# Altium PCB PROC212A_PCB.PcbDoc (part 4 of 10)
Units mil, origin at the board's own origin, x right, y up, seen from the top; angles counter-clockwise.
Board outline 3032.48 x 3598.78 mil, 4 copper layers (Top Layer, L2_GND1, L3_PWR1, Bottom Layer), stack 60.58 mil thick; 432 components, 310 nets, 7775 pads, 1236 vias.
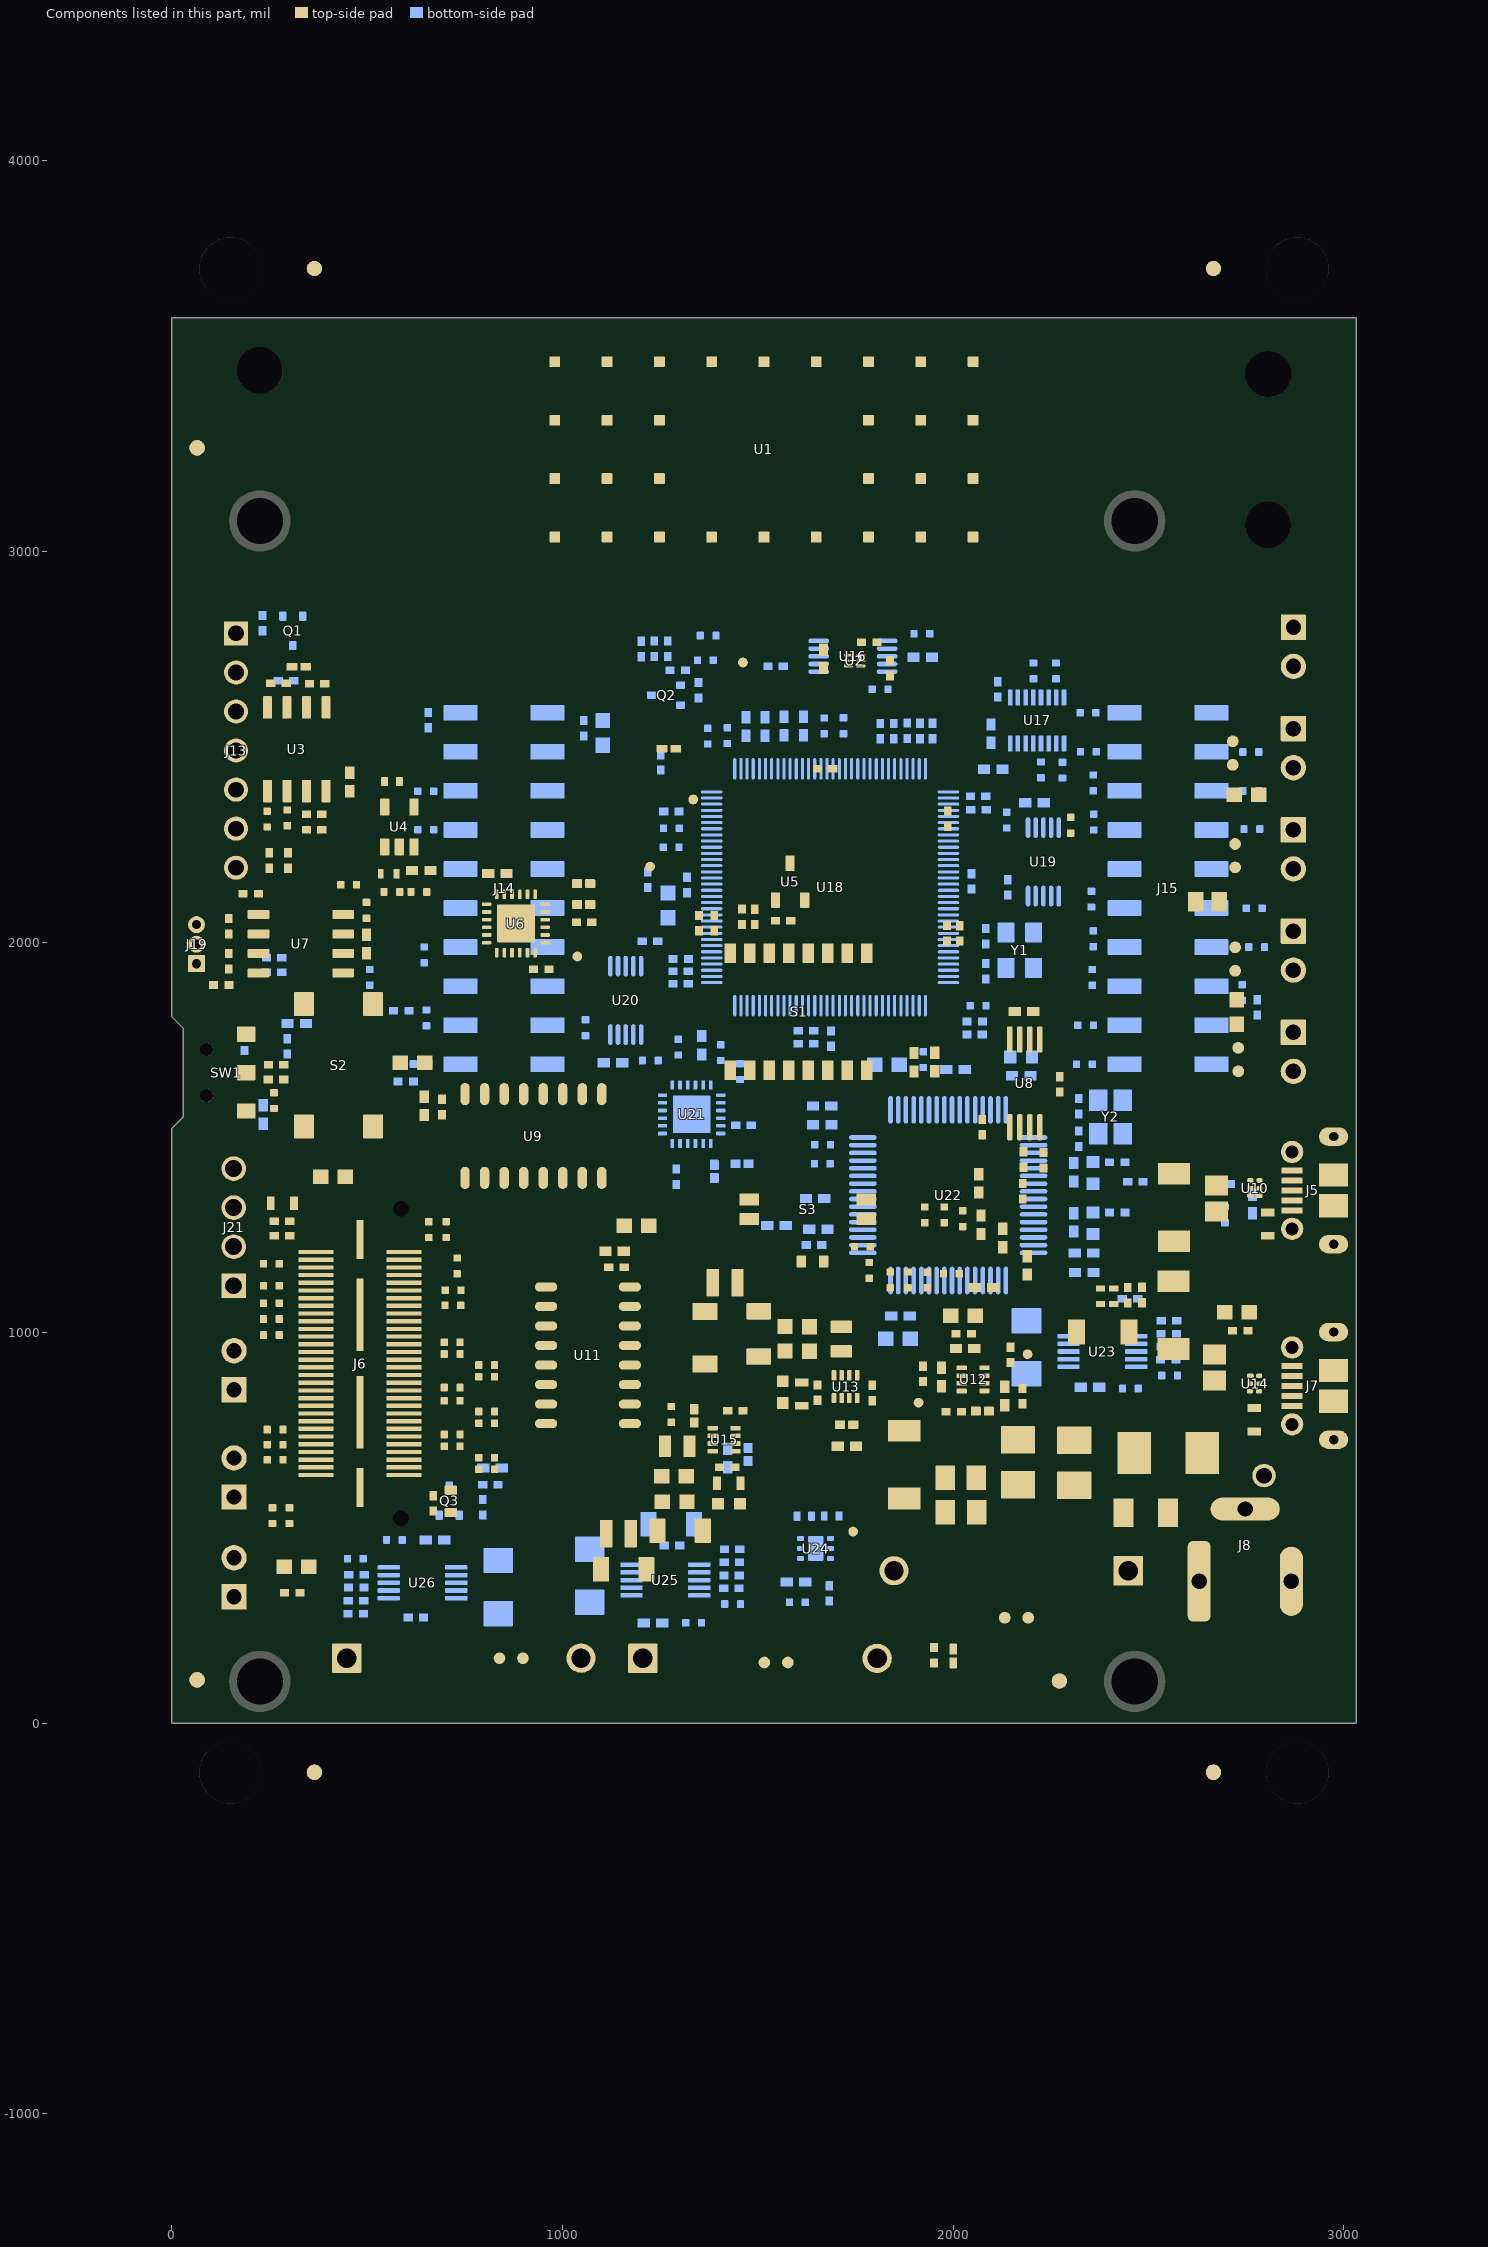
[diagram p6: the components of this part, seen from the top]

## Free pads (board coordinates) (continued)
  round 6 on Mech16: 1(585.22,1972.52) 1(585.22,1972.52) 1(585.22,2004.02) 1(585.22,2004.02) 1(589.23,1869.52) 1(589.23,1869.52) 1(589.23,1901.02) 1(589.23,1901.02) 1(598.22,1670.52) 1(598.22,1670.52) 1(598.22,1702.02) 1(598.22,1702.02) 1(600.22,1772.52) 1(600.22,1772.52) 1(600.22,1804.02) 1(600.22,1804.02) 1(605.74,1972.52) 1(605.74,2004.02) 1(609.76,1869.52) 1(609.76,1901.02) 1(618.75,1670.52) 1(618.75,1702.02) 1(620.75,1772.52) 1(620.75,1804.02) 1(623.74,1972.52) 1(623.74,2004.02) 1(627.76,1869.52) 1(627.76,1901.02) 1(630.28,289.75) 1(631.28,339.75) 1(633.28,341.75) 1(633.28,341.75) 1(633.28,389.75) 1(633.28,389.75) 1(636.75,1670.52) 1(636.75,1702.02) 1(638.75,1772.52) 1(638.75,1804.02) 1(644.27,1972.52) 1(644.27,1972.52) 1(644.27,2004.02) 1(644.27,2004.02) 1(644.28,289.75) 1(644.28,289.75) 1(644.28,400.75) 1(648.29,1869.52) 1(648.29,1869.52) 1(648.29,1901.02) 1(648.29,1901.02) 1(657.28,1670.52) 1(657.28,1670.52) 1(657.28,1702.02) 1(657.28,1702.02) 1(659.28,1772.52) 1(659.28,1772.52) 1(659.28,1804.02) 1(659.28,1804.02) 1(659.28,304.75) 1(710,1170.75) 1(710,1170.75) 1(710,1191.28) 1(710,1209.28) 1(710,1229.81) 1(710,1229.81) 1(713.28,1148.75) 1(741.5,1170.75) 1(741.5,1170.75) 1(741.5,1191.28) 1(741.5,1209.28) 1(741.5,1229.81) 1(741.5,1229.81) 1(745.28,1148.75) 1(745.28,1148.75) 1(746.28,1149.75) 1(814.37,1002.35) 1(814.37,1002.35) 1(814.37,1022.88) 1(814.37,1040.88) 1(814.37,1061.4) 1(814.37,1061.4) 1(814.37,1072.35) 1(814.37,1072.35) 1(814.37,1092.88) 1(814.37,1110.88) 1(814.37,1131.4) 1(814.37,1131.4) 1(845.87,1002.35) 1(845.87,1002.35) 1(845.87,1022.88) 1(845.87,1040.88) 1(845.87,1061.4) 1(845.87,1061.4) 1(845.87,1072.35) 1(845.87,1072.35) 1(845.87,1092.88) 1(845.87,1110.88) 1(845.87,1131.4) 1(845.87,1131.4) 1(939.13,2721.18) 1(939.13,2721.18) 1(939.13,3213.22) 1(939.13,3213.22) 1(946.57,2728.78) 1(946.57,2728.78) 1(946.57,2903.18) 1(946.57,2903.18) 1(946.65,2728.7) 1(946.65,2728.7) 1(946.65,2903.14) 1(946.65,2903.14) 1(985.49,3163.74) 1(985.49,3163.74) 1(987.37,3170.58) 1(987.37,3170.58) 1(987.49,3155.02) 1(987.49,3155.02) 1(987.53,3170.82) 1(987.53,3170.82) 1(987.61,2785.1) 1(987.61,2785.1) 1(987.61,2802.02) 1(987.61,2802.02) 1(989.73,2785.1) 1(989.73,2785.1) 1(989.73,2799.14) 1(989.73,2799.14) 1(989.81,2799.14) 1(989.81,2799.14) 1(990.69,2802.02) 1(990.69,2802.02) 1(990.97,3162.46) 1(990.97,3162.46) 1(991.85,3167.62) 1(991.85,3167.62) 1(991.93,3167.78) 1(991.93,3167.78) 1(992.45,3157.02) 1(992.45,3157.02) 1(993.17,3175.02) 1(993.17,3175.02) 1(995.09,2785.1) 1(995.09,2785.1) 1(996.05,2787.78) 1(996.05,2787.78) 1(996.37,3170.42) 1(996.37,3170.42) 1(996.97,2785.1) 1(996.97,2785.1) 1(997.13,3148.3) 1(997.13,3148.3) 1(999.45,3136.1) 1(999.45,3136.1) 1(1001.37,2802.02) 1(1001.37,2802.02) 1(1002.01,3171.02) 1(1002.01,3171.02) 1(1002.05,3176.38) 1(1002.05,3176.38) 1(1002.29,2799.14) 1(1002.29,2799.14) 1(1002.33,2785.1) 1(1002.33,2785.1) 1(1002.33,2799.14) 1(1002.33,2799.14) 1(1004.45,2785.1) 1(1004.45,2785.1) 1(1004.45,2802.02) 1(1004.45,2802.02) 1(1004.49,3138.34) 1(1004.49,3138.34) 1(1006.33,2800.1) 1(1006.33,2800.1) 1(1006.33,2802.02) 1(1006.33,2802.02) 1(1012.01,2785.1) 1(1012.01,2785.1) 1(1012.01,2800.1) 1(1012.01,2800.1) 1(1012.01,3169.82) 1(1012.01,3169.82) 1(1012.13,3175.26) 1(1012.13,3175.26) 1(1014.21,3127.54) 1(1014.21,3127.54) 1(1014.25,2785.1) 1(1014.25,2785.1) 1(1014.25,2800.1) 1(1014.25,2800.1) 1(1019.89,2800.1) 1(1019.89,2800.1) 1(1019.89,2802.02) 1(1019.89,2802.02) 1(1019.97,3114.5) 1(1019.97,3114.5) 1(1020.53,2831.54) 1(1020.53,2831.54) 1(1020.53,2851.94) 1(1020.53,2851.94) 1(1021.29,2856.34) 1(1021.29,2856.34) 1(1022.57,2762.58) 1(1022.57,2762.58) 1(1022.57,2803.58) 1(1022.57,2803.58) 1(1023.41,2859.5) 1(1023.41,2859.5) 1(1024.01,3172.18) 1(1024.01,3172.18) 1(1024.13,3166.54) 1(1024.13,3166.54) 1(1026.05,3116.18) 1(1026.05,3116.18) 1(1026.69,2861.42) 1(1026.69,2861.42) 1(1027.09,2831.54) 1(1027.09,2831.54) 1(1027.09,2850.22) 1(1027.09,2850.22) 1(1028.61,2855.3) 1(1028.61,2855.3) 1(1029.69,3127.5) 1(1029.69,3127.5) 1(1030.17,2762.58) 1(1030.17,2762.58) 1(1030.17,2765.82) 1(1030.17,2765.82) 1(1030.29,2765.82) 1(1030.29,2765.82) 1(1030.49,2778.02) 1(1030.49,2778.02) 1(1030.49,2790.62) 1(1030.49,2790.62) 1(1030.49,2803.58) 1(1030.49,2803.58) 1(1030.58,-214.18) 1(1030.61,2790.62) 1(1030.61,2790.62) 1(1030.69,2773.62) 1(1030.69,2773.62) 1(1030.69,2782.46) 1(1030.69,2782.46) 1(1031.09,2862.06) 1(1031.09,2862.06) 1(1031.29,2770.42) 1(1031.29,2770.42) 1(1031.29,2785.62) 1(1031.29,2785.62) 1(1032.57,2768.5) 1(1032.57,2768.5) 1(1032.57,2787.54) 1(1032.57,2787.54) 1(1032.89,2856.9) 1(1032.89,2856.9) 1(1033.29,2762.74) 1(1033.29,2762.74) 1(1033.45,2793.38) 1(1033.45,2793.38) 1(1034.73,2767.86) 1(1034.73,2767.86) 1(1034.73,2788.18) 1(1034.73,2788.18) 1(1035.89,2856.3) 1(1035.89,2856.3) 1(1036.09,3138.66) 1(1036.09,3138.66) 1(1036.37,2860.74) 1(1036.37,2860.74) 1(1036.81,2768.5) 1(1036.81,2768.5) 1(1036.81,2787.54) 1(1036.81,2787.54) 1(1037.29,2761.74) 1(1037.29,2761.74) 1(1037.29,2794.26) 1(1037.29,2794.26) 1(1037.33,3167.38) 1(1037.33,3167.38) 1(1037.97,3161.34) 1(1037.97,3161.34) 1(1038.09,2770.42) 1(1038.09,2770.42) 1(1038.09,2785.62) 1(1038.09,2785.62) 1(1038.13,2854.62) 1(1038.13,2854.62) 1(1038.69,2773.58) 1(1038.69,2773.58) 1(1038.69,2782.46) 1(1038.69,2782.46) 1(1038.85,2778.02) 1(1038.85,2778.02) 1(1039.57,2852.14) 1(1039.57,2852.14) 1(1039.75,-228.78) 1(1039.75,-223.35) 1(1039.75,-223.35) 1(1039.97,2857.34) 1(1039.97,2857.34) 1(1040.09,2831.54) 1(1040.09,2831.54) 1(1040.09,2849.06) 1(1040.09,2849.06) 1(1040.09,2857.34) 1(1040.09,2857.34) 1(1040.09,2872.58) 1(1040.09,2872.58) 1(1041.53,2762.66) 1(1041.53,2762.66) 1(1041.53,2793.34) 1(1041.53,2793.34) 1(1044.25,3148.14) 1(1044.25,3148.14) 1(1044.49,2765.58) 1(1044.49,2765.58) 1(1044.49,2790.46) 1(1044.49,2790.46) 1(1046.21,2770.62) 1(1046.21,2770.62) 1(1046.21,2785.42) 1(1046.21,2785.42) 1(1046.29,3092.66) 1(1046.29,3092.66) 1(1046.65,2831.54) 1(1046.65,2831.54) 1(1046.65,2872.58) 1(1046.65,2872.58) 1(1046.77,2778.02) 1(1046.77,2778.02) 1(1051.29,2762.58) 1(1051.29,2762.58) 1(1051.65,3161.02) 1(1051.65,3161.02) 1(1051.89,2831.58) 1(1051.89,2831.58) 1(1051.89,2836.66) 1(1051.89,2836.66) 1(1051.89,2856.38) 1(1051.89,2856.38) 1(1051.89,2861.26) 1(1051.89,2861.26) 1(1052.05,2765.14) 1(1052.05,2765.14) 1(1052.25,2768.54) 1(1052.25,2768.54) 1(1052.25,2784.82) 1(1052.25,2784.82) 1(1052.65,2788.62) 1(1052.65,2788.62) 1(1053.09,3154.38) 1(1053.09,3154.38) 1(1054.33,2791.62) 1(1054.33,2791.62) 1(1054.65,2836.42) 1(1054.65,2836.42) 1(1056.13,2831.26) 1(1056.13,2831.26) 1(1057.33,2837.46) 1(1057.33,2837.46) 1(1057.73,2793.58) 1(1057.73,2793.58) 1(1057.81,2840.5) 1(1057.81,2840.5) 1(1057.81,2856.38) 1(1057.81,2856.38) 1(1057.81,2861.26) 1(1057.81,2861.26) 1(1057.81,2870.18) 1(1057.81,2870.18) 1(1058.85,2762.58) 1(1058.85,2762.58) 1(1059.85,2765.78) 1(1059.85,2765.78) 1(1059.85,2771.94) 1(1059.85,2771.94) 1(1059.85,2778.02) 1(1059.85,2778.02) 1(1059.85,2785.1) 1(1059.85,2785.1) 1(1059.93,2765.78) 1(1059.93,2765.78) 1(1060.29,2831.74) 1(1060.29,2831.74) 1(1060.53,2782.74) 1(1060.53,2782.74) 1(1060.69,2787.86) 1(1060.69,2787.86) 1(1061.49,2768.26) 1(1061.49,2768.26) 1(1062.77,2833.22) 1(1062.77,2833.22) 1(1062.93,3087.38) 1(1062.93,3087.38) 1(1062.97,2781.46) 1(1062.97,2781.46) 1(1063.13,2762.58) 1(1063.13,2762.58) 1(1063.21,2776.46) 1(1063.21,2776.46) 1(1063.45,2794.26) 1(1063.45,2794.26) 1(1063.49,2788.86) 1(1063.49,2788.86) 1(1063.97,2835.58) 1(1063.97,2835.58) 1(1064.33,2838.86) 1(1064.33,2838.86) 1(1064.33,2856.38) 1(1064.33,2856.38) 1(1064.33,2861.26) 1(1064.33,2861.26) 1(1064.33,2870.18) 1(1064.33,2870.18) 1(1064.73,2767.14) 1(1064.73,2767.14) 1(1066.25,2787.78) 1(1066.25,2787.78) 1(1066.25,3100.42) 1(1066.25,3100.42) 1(1066.53,3153.34) 1(1066.53,3153.34) 1(1066.69,2774.74) 1(1066.69,2774.74) 1(1067.01,2768.42) 1(1067.01,2768.42) 1(1067.17,2784.02) 1(1067.17,2784.02) 1(1067.17,2784.86) 1(1067.17,2784.86) 1(1067.49,2780.26) 1(1067.49,2780.26) 1(1067.69,2771.46) 1(1067.69,2771.46) 1(1067.69,2793.78) 1(1067.69,2793.78) 1(1067.81,2761.74) 1(1067.81,2761.74) 1(1069.29,2856.38) 1(1069.29,2856.38) 1(1069.29,2861.26) 1(1069.29,2861.26) 1(1071.01,2778.94) 1(1071.01,2778.94) 1(1071.13,2792.18) 1(1071.13,2792.18) 1(1071.33,2762.54) 1(1071.33,2762.54) 1(1073.41,2777.06) 1(1073.41,2777.06) 1(1073.45,2789.26) 1(1073.45,2789.26) 1(1073.61,2764.62) 1(1073.61,2764.62) 1(1073.61,3113.54) 1(1073.61,3113.54) 1(1073.93,2831.54) 1(1073.93,2831.54) 1(1073.93,2861.26) 1(1073.93,2861.26) 1(1073.93,2866.38) 1(1073.93,2866.38) 1(1073.93,2872.58) 1(1073.93,2872.58) 1(1074.29,2784.02) 1(1074.29,2784.02) 1(1074.29,2784.74) 1(1074.29,2784.74) 1(1074.85,2774.34) 1(1074.85,2774.34) 1(1074.89,2767.5) 1(1074.89,2767.5) 1(1075.28,1156.98) 1(1075.28,1156.98) 1(1075.28,1165.75) 1(1075.29,2770.62) 1(1075.29,2770.62) 1(1075.61,3073.06) 1(1075.61,3073.06) 1(1076.21,2791.3) 1(1076.21,2791.3) 1(1076.81,2795.82) 1(1076.81,2795.82) 1(1077.17,2785.78) 1(1077.17,2785.78) 1(1078.69,2799.74) 1(1078.69,2799.74) 1(1079.65,3070.7) 1(1079.65,3070.7) 1(1079.81,2781.94) 1(1079.81,2781.94) 1(1080.49,2831.54) 1(1080.49,2831.54) 1(1080.49,2861.26) 1(1080.49,2861.26) 1(1080.49,2866.38) 1(1080.49,2866.38) 1(1080.49,2872.58) 1(1080.49,2872.58) 1(1081.61,3144.58) 1(1081.61,3144.58) 1(1082.17,2802.54) 1(1082.17,2802.54) 1(1082.37,1149.89) 1(1082.53,3051.38) 1(1082.53,3051.38) 1(1083.33,3124.3) 1(1083.33,3124.3) 1(1083.93,2779.7) 1(1083.93,2779.7) 1(1084.49,2791.18) 1(1084.49,2791.18) 1(1085.41,2861.26) 1(1085.41,2861.26) 1(1085.49,3097.78) 1(1085.49,3097.78) 1(1085.81,2795.86) 1(1085.81,2795.86) 1(1086.01,2786.54) 1(1086.01,2786.54) 1(1086.65,3052.06) 1(1086.65,3052.06) 1(1087.36,1856.23) 1(1087.36,1856.23) 1(1087.36,1856.23) 1(1087.49,2803.58) 1(1087.49,2803.58) 1(1089.25,2778.94) 1(1089.25,2778.94) 1(1090.01,2785.02) 1(1090.01,2785.02) 1(1090.25,2797.5) 1(1090.25,2797.5) 1(1091.29,3106.3) 1(1091.29,3106.3) 1(1092.05,2861.26) 1(1092.05,2861.26) 1(1093.05,3130.82) 1(1093.05,3130.82) 1(1093.69,2762.58) 1(1093.69,2762.58) 1(1093.69,2778.94) 1(1093.69,2778.94) 1(1093.69,2785.02) 1(1093.69,2785.02) 1(1093.69,2797.5) 1(1093.69,2797.5) 1(1093.73,3130.26) 1(1093.73,3130.26) 1(1094.69,2831.54) 1(1094.69,2831.54) 1(1095.69,3068.22) 1(1095.69,3068.22) 1(1095.86,1847.73) 1(1095.86,1847.73) 1(1095.86,1864.73) 1(1095.86,1864.73) 1(1096.41,3134.9) 1(1096.41,3134.9) 1(1097.93,3033.86) 1(1097.93,3033.86) 1(1098.09,2839.06) 1(1098.09,2839.06) 1(1098.21,2839.06) 1(1098.21,2839.06) 1(1098.38,-230.78) 1(1098.38,-219.79) 1(1098.38,-219.79) 1(1098.38,-219.78) 1(1101.29,3059.78) 1(1101.29,3059.78) 1(1101.41,2831.54) 1(1101.41,2831.54) 1(1101.97,2762.58) 1(1101.97,2762.58) 1(1101.97,2803.58) 1(1101.97,2803.58) 1(1103.21,3034.46) 1(1103.21,3034.46) 1(1103.57,2861.26) 1(1103.57,2861.26) 1(1106.93,2853.62) 1(1106.93,2853.62) 1(1107.05,2853.62) 1(1107.05,2853.62) 1(1109.17,2762.58) 1(1109.17,2762.58) 1(1109.17,2785.5) 1(1109.17,2785.5) 1(1109.69,2789.42) 1(1109.69,2789.42) 1(1110.17,2861.26) 1(1110.17,2861.26) 1(1110.61,3124.54) 1(1110.61,3124.54) 1(1111.25,2792.18) 1(1111.25,2792.18) 1(1112.53,2831.54) 1(1112.53,2831.54) 1(1113.73,2793.78) 1(1113.73,2793.78) 1(1114.29,3121.66) 1(1114.29,3121.66) 1(1115.41,3025.94) 1(1115.41,3025.94) 1(1115.73,2839.06) 1(1115.73,2839.06) 1(1115.85,2839.06) 1(1115.85,2839.06) 1(1117.05,2794.26) 1(1117.05,2794.26) 1(1117.09,2762.58) 1(1117.09,2762.58) 1(1117.09,2783.86) 1(1117.09,2783.86) 1(1117.17,3020.46) 1(1117.17,3020.46) 1(1117.33,3039.9) 1(1117.33,3039.9) 1(1117.89,2787.18) 1(1117.89,2787.18) 1(1118.13,3046.14) 1(1118.13,3046.14) 1(1118.57,3034.18) 1(1118.57,3034.18) 1(1119.41,2831.54) 1(1119.41,2831.54) 1(1120.49,2788.18) 1(1120.49,2788.18) 1(1121.17,3040.06) 1(1121.17,3040.06) 1(1121.21,3029.42) 1(1121.21,3029.42) 1(1121.49,2793.3) 1(1121.49,2793.3) 1(1121.65,2861.26) 1(1121.65,2861.26) 1(1121.69,3052.38) 1(1121.69,3052.38) 1(1121.73,3052.42) 1(1121.73,3052.42) 1(1121.81,3045.02) 1(1121.81,3045.02) 1(1121.93,3126.74) 1(1121.93,3126.74) 1(1122.17,3035.5) 1(1122.17,3035.5) 1(1122.65,3027.46) 1(1122.65,3027.46) 1(1122.69,3107.54) 1(1122.69,3107.54) 1(1123.61,2786.94) 1(1123.61,2786.94) 1(1124.25,3031.7) 1(1124.25,3031.7) 1(1124.57,2790.34) 1(1124.57,2790.34) 1(1124.65,3049.94) 1(1124.65,3049.94) 1(1124.69,2762.58) 1(1124.69,2762.58) 1(1124.69,2783.06) 1(1124.69,2783.06) 1(1124.69,2790.34) 1(1124.69,2790.34) 1(1124.69,2803.58) 1(1124.69,2803.58) 1(1124.77,3050.1) 1(1124.77,3050.1) 1(1124.93,3057.14) 1(1124.93,3057.14) 1(1125.73,3023.26) 1(1125.73,3023.26) 1(1125.73,3029.7) 1(1125.73,3029.7) 1(1128.61,2861.26) 1(1128.61,2861.26) 1(1129.61,3018.18) 1(1129.61,3018.18) 1(1131.01,3022.62) 1(1131.01,3022.62) 1(1131.97,3067.46) 1(1131.97,3067.46) 1(1132.45,3105.58) 1(1132.45,3105.58) 1(1132.61,2762.58) 1(1132.61,2762.58) 1(1132.61,2803.58) 1(1132.61,2803.58) 1(1133.33,3126.1) 1(1133.33,3126.1) 1(1134.21,3121.98) 1(1134.21,3121.98) 1(1135.17,3065.38) 1(1135.17,3065.38) 1(1135.61,3011.18) 1(1135.61,3011.18) 1(1136.57,3074.26) 1(1136.57,3074.26) 1(1137.29,2774.38) 1(1137.29,2774.38) 1(1137.29,2782.34) 1(1137.29,2782.34) 1(1137.81,3014.22) 1(1137.81,3014.22) 1(1137.93,2769.02) 1(1137.93,2769.02) 1(1137.97,2787.26) 1(1137.97,2787.26) 1(1139.69,3072.02) 1(1139.69,3072.02) 1(1140.01,2765.02) 1(1140.01,2765.02) 1(1140.09,2791.02) 1(1140.09,2791.02) 1(1140.37,3042.94) 1(1140.37,3042.94) 1(1143.49,3045.14) 1(1143.49,3045.14) 1(1143.53,2793.42) 1(1143.53,2793.42) 1(1143.53,3084.54) 1(1143.53,3084.54) 1(1143.65,2762.58) 1(1143.65,2762.58) 1(1144.49,3123.06) 1(1144.49,3123.06) 1(1144.85,2774.38) 1(1144.85,2774.38) 1(1144.85,2782.34) 1(1144.85,2782.34) 1(1145.53,2786.54) 1(1145.53,2786.54) 1(1145.77,2768.9) 1(1145.77,2768.9) 1(1146.77,3089.22) 1(1146.77,3089.22) 1(1146.81,3089.26) 1(1146.81,3089.26) 1(1147.93,2840.38) 1(1147.93,2840.38) 1(1148.33,2794.26) 1(1148.33,2794.26) 1(1148.41,2788.54) 1(1148.41,2788.54) 1(1148.69,2767.14) 1(1148.69,2767.14) 1(1148.77,2844.06) 1(1148.77,2844.06) 1(1148.93,2852.94) 1(1148.93,2852.94) 1(1149.05,2761.74) 1(1149.05,2761.74) 1(1149.17,2835.9) 1(1149.17,2835.9) 1(1150.13,3087.42) 1(1150.13,3087.42) 1(1150.33,2857.14) 1(1150.33,2857.14) 1(1150.77,2787.9) 1(1150.77,2787.9) 1(1150.89,2767.78) 1(1150.89,2767.78) 1(1150.97,2846.54) 1(1150.97,2846.54) 1(1151.29,3094.9) 1(1151.29,3094.9) 1(1152.17,2769.7) 1(1152.17,2769.7) 1(1152.17,2785.94) 1(1152.17,2785.94) 1(1152.25,2832.94) 1(1152.25,2832.94) 1(1152.81,2773.06) 1(1152.81,2773.06) 1(1152.81,2782.62) 1(1152.81,2782.62) 1(1152.97,2777.94) 1(1152.97,2777.94) 1(1153.13,2859.98) 1(1153.13,2859.98) 1(1153.41,2793.54) 1(1153.41,2793.54) 1(1153.69,3091.9) 1(1153.69,3091.9) 1(1154.01,2848.1) 1(1154.01,2848.1) 1(1154.25,2762.54) 1(1154.25,2762.54) 1(1154.49,2839.82) 1(1154.49,2839.82) 1(1155.09,2837.78) 1(1155.09,2837.78) 1(1155.29,3118.22) 1(1155.29,3118.22) 1(1155.41,2841.9) 1(1155.41,2841.9) 1(1155.73,2852.94) 1(1155.73,2852.94) 1(1155.81,3068.1) 1(1155.81,3068.1) 1(1156.05,3067.98) 1(1156.05,3067.98) 1(1156.57,2831.26) 1(1156.57,2831.26) 1(1156.65,3113.06) 1(1156.65,3113.06) 1(1156.77,3097.94) 1(1156.77,3097.94) 1(1156.81,2836.62) 1(1156.81,2836.62) 1(1156.93,2861.58) 1(1156.93,2861.58) 1(1157.25,3026.82) 1(1157.25,3026.82) 1(1157.33,3071.58) 1(1157.33,3071.58) 1(1157.37,2790.9) 1(1157.37,2790.9) 1(1157.53,2849.06) 1(1157.53,2849.06) 1(1157.53,3071.5) 1(1157.53,3071.5) 1(1157.61,2843.18) 1(1157.61,2843.18) 1(1157.89,2856.06) 1(1157.89,2856.06) 1(1157.93,2765.22) 1(1157.93,2765.22) 1(1158.05,3094.3) 1(1158.05,3094.3) 1(1159.01,2836.06) 1(1159.01,2836.06) 1(1159.97,2785.9) 1(1159.97,2785.9) 1(1160.17,2770.26) 1(1160.17,2770.26) 1(1160.69,2844.02) 1(1160.69,2844.02) 1(1160.89,2778.02) 1(1160.89,2778.02) 1(1161.09,2835.9) 1(1161.09,2835.9) 1(1161.09,2849.82) 1(1161.09,2849.82) 1(1161.21,2830.74) 1(1161.21,2830.74) 1(1161.33,2862.06) 1(1161.33,2862.06) 1(1161.77,2856.9) 1(1161.77,2856.9) 1(1161.85,3048.02) 1(1161.85,3048.02) 1(1162.57,3098.86) 1(1162.57,3098.86) 1(1162.69,3095.06) 1(1162.69,3095.06) 1(1164.17,2850.66) 1(1164.17,2850.66) 1(1164.21,2844.78) 1(1164.21,2844.78) 1(1164.89,3040.62) 1(1164.89,3040.62) 1(1165.21,2856.34) 1(1165.21,2856.34) 1(1165.45,3112.1) 1(1165.45,3112.1) 1(1165.53,2861.66) 1(1165.53,2861.66) 1(1165.57,2762.58) 1(1165.57,2762.58) 1(1165.57,2785.5) 1(1165.57,2785.5) 1(1165.65,2837.06) 1(1165.65,2837.06) 1(1165.69,3053.62) 1(1165.69,3053.62) 1(1166.09,2789.42) 1(1166.09,2789.42) 1(1166.37,2851.9) 1(1166.37,2851.9) 1(1166.41,2831.38) 1(1166.41,2831.38) 1(1166.97,3094.46) 1(1166.97,3094.46) 1(1167.17,2853.86) 1(1167.17,2853.86) 1(1167.65,2792.18) 1(1167.65,2792.18) 1(1167.73,2845.74) 1(1167.73,2845.74) 1(1167.81,2841.06) 1(1167.81,2841.06) 1(1167.81,2841.1) 1(1167.81,2841.1) 1(1167.89,3042.98) 1(1167.89,3042.98) 1(1167.97,3098.18) 1(1167.97,3098.18) 1(1168.49,3007.94) 1(1168.49,3007.94) 1(1169.05,3104.86) 1(1169.05,3104.86) 1(1169.33,3062.22) 1(1169.33,3062.22) 1(1169.37,3093.86) 1(1169.37,3093.86) 1(1169.57,2860.26) 1(1169.57,2860.26) 1(1170.09,2793.78) 1(1170.09,2793.78) 1(1170.33,3097.58) 1(1170.33,3097.58) 1(1170.57,2833.3) 1(1170.57,2833.3) 1(1170.77,2847.3) 1(1170.77,2847.3) 1(1170.93,3065.7) 1(1170.93,3065.7) 1(1171.45,3010.54) 1(1171.45,3010.54) 1(1172.57,2857.62) 1(1172.57,2857.62) 1(1172.93,2849.78) 1(1172.93,2849.78) 1(1173.33,2836.5) 1(1173.33,2836.5) 1(1173.41,2794.26) 1(1173.41,2794.26) 1(1173.49,2762.58) 1(1173.49,2762.58) 1(1173.49,2783.86) 1(1173.49,2783.86) 1(1173.73,2853.54) 1(1173.73,2853.54) 1(1174.29,2787.18) 1(1174.29,2787.18) 1(1174.41,2841.1) 1(1174.41,2841.1) 1(1174.81,3105.26) 1(1174.81,3105.26) 1(1175.37,3096.22) 1(1175.37,3096.22) 1(1176.49,2831.54) 1(1176.49,2831.54) 1(1176.89,2788.18) 1(1176.89,2788.18) 1(1177.61,2861.26) 1(1177.61,2861.26) 1(1177.89,3091.54) 1(1177.89,3091.54) 1(1177.97,2793.22) 1(1177.97,2793.22) 1(1179.97,2786.94) 1(1179.97,2786.94) 1(1181.09,2762.58) 1(1181.09,2762.58) 1(1181.09,2783.06) 1(1181.09,2783.06) 1(1181.29,2789.86) 1(1181.29,2789.86) 1(1181.41,2789.86) 1(1181.41,2789.86) 1(1181.41,2793.46) 1(1181.41,2793.46) 1(1181.41,3022.22) 1(1181.41,3022.22) 1(1181.49,3094.5) 1(1181.49,3094.5) 1(1183.13,3098.18) 1(1183.13,3098.18) 1(1184.13,3024.94) 1(1184.13,3024.94) 1(1184.37,3055.26) 1(1184.37,3055.26) 1(1184.49,2831.54) 1(1184.49,2831.54) 1(1184.61,3069.34) 1(1184.61,3069.34) 1(1185.29,3073.06) 1(1185.29,3073.06) 1(1185.65,2861.26) 1(1185.65,2861.26) 1(1186.13,3058.66) 1(1186.13,3058.66) 1(1186.41,2996.1) 1(1186.41,2996.1) 1(1188.21,3088.3) 1(1188.21,3088.3) 1(1188.97,2850.34) 1(1188.97,2850.34) 1(1189.01,2762.58) 1(1189.01,2762.58) 1(1189.01,2793.46) 1(1189.01,2793.46) 1(1190.17,3091.5) 1(1190.17,3091.5) 1(1193.57,2845.98) 1(1193.57,2845.98) 1(1194.81,2762.58) 1(1194.81,2762.58) 1(1194.81,2793.46) 1(1194.81,2793.46) 1(1197.49,2831.54) 1(1197.49,2831.54) 1(1197.49,2842.18) 1(1197.49,2842.18) 1(1197.49,2849.26) 1(1197.49,2849.26) 1(1197.49,2872.58) 1(1197.49,2872.58) 1(1198.41,2981.3) 1(1198.41,2981.3) 1(1200.33,3005.94) 1(1200.33,3005.94) 1(1200.85,3046.78) 1(1200.85,3046.78) 1(1202.37,2762.58) 1(1202.37,2762.58) 1(1202.37,2766.18) 1(1202.37,2766.18) 1(1202.37,2983.26) 1(1202.37,2983.26) 1(1202.49,2766.18) 1(1202.49,2766.18) 1(1202.57,3064.18) 1(1202.57,3064.18) 1(1202.73,2772.94) 1(1202.73,2772.94) 1(1202.73,2793.46) 1(1202.73,2793.46) 1(1202.73,3008.94) 1(1202.73,3008.94) 1(1202.77,3050.1) 1(1202.77,3050.1) 1(1203.73,3067.82) 1(1203.73,3067.82) 1(1203.81,2769.1) 1(1203.81,2769.1) 1(1204.01,2872.58) 1(1204.01,2872.58) 1(1204.05,2831.54) 1(1204.05,2831.54) 1(1204.05,2872.58) 1(1204.05,2872.58) 1(1205.81,2762.82) 1(1205.81,2762.82) 1(1206.93,2767.86) 1(1206.93,2767.86) 1(1207.61,2855.58) 1(1207.61,2855.58) 1(1207.61,2861.9) 1(1207.61,2861.9) 1(1209.4,1856.23) 1(1209.53,2768.86) 1(1209.53,2768.86) 1(1210.05,2862.06) 1(1210.05,2862.06) 1(1210.33,2772.14) 1(1210.33,2772.14) 1(1210.33,2793.46) 1(1210.33,2793.46) 1(1210.37,2761.74) 1(1210.37,2761.74) 1(1210.41,2855.86) 1(1210.41,2855.86) 1(1213.05,2861.5) 1(1213.05,2861.5) 1(1213.57,2855.18) 1(1213.57,2855.18) 1(1213.69,2762.26) 1(1213.69,2762.26) 1(1215.65,2859.98) 1(1215.65,2859.98) 1(1216.13,2853.22) 1(1216.13,2853.22) 1(1216.17,2763.86) 1(1216.17,2763.86) 1(1216.37,2969.3) 1(1216.37,2969.3) 1(1217.65,2857.86) 1(1217.65,2857.86) 1(1217.73,2766.62) 1(1217.73,2766.62) 1(1217.85,2850.06) 1(1217.85,2850.06) 1(1218.25,2770.54) 1(1218.25,2770.54) 1(1218.25,2793.46) 1(1218.25,2793.46) 1(1218.45,2831.54) 1(1218.45,2831.54) 1(1218.45,2845.7) 1(1218.45,2845.7) 1(1218.49,3036.5) 1(1218.49,3036.5) 1(1218.77,2855.5) 1(1218.77,2855.5) 1(1218.85,2855.5) 1(1218.85,2855.5) 1(1218.85,2861.26) 1(1218.85,2861.26) 1(1219.65,2971.86) 1(1219.65,2971.86) 1(1220.57,3039.7) 1(1220.57,3039.7) 1(1222.33,3055.18) 1(1222.33,3055.18) 1(1222.49,2991.14) 1(1222.49,2991.14) 1(1223.49,2762.58) 1(1223.49,2762.58) 1(1223.89,3058.66) 1(1223.89,3058.66) 1(1224.29,2765.14) 1(1224.29,2765.14) 1(1224.45,2768.54) 1(1224.45,2768.54) 1(1224.45,2784.82) 1(1224.45,2784.82) 1(1224.53,2994.38) 1(1224.53,2994.38) 1(1224.89,2788.62) 1(1224.89,2788.62) 1(1225.01,2831.54) 1(1225.01,2831.54) 1(1225.01,2861.26) 1(1225.01,2861.26) 1(1226.53,2791.62) 1(1226.53,2791.62) 1(1229.97,2793.58) 1(1229.97,2793.58) 1(1231.09,2762.58) 1(1231.09,2762.58) 1(1231.09,2846.42) 1(1231.09,2846.42) 1(1232.05,2765.78) 1(1232.05,2765.78) 1(1232.05,2771.94) 1(1232.05,2771.94) 1(1232.05,2778.02) 1(1232.05,2778.02) 1(1232.05,2785.1) 1(1232.05,2785.1) 1(1232.09,2840.14) 1(1232.09,2840.14) 1(1232.09,2852.7) 1(1232.09,2852.7) 1(1232.17,2765.78) 1(1232.17,2765.78) 1(1232.77,2782.74) 1(1232.77,2782.74) 1(1232.89,2787.86) 1(1232.89,2787.86) 1(1233.69,2768.26) 1(1233.69,2768.26) 1(1235.01,2835.14) 1(1235.01,2835.14) 1(1235.01,2857.66) 1(1235.01,2857.66) 1(1235.21,2781.46) 1(1235.21,2781.46) 1(1235.37,2762.58) 1(1235.37,2762.58) 1(1235.45,2776.46) 1(1235.45,2776.46) 1(1235.69,2794.26) 1(1235.69,2794.26) 1(1235.73,2788.86) 1(1235.73,2788.86) 1(1236.37,2958.42) 1(1236.37,2958.42) 1(1236.93,2767.14) 1(1236.93,2767.14) 1(1236.97,3024.1) 1(1236.97,3024.1) 1(1237.61,2846.42) 1(1237.61,2846.42) 1(1238.09,2842.62) 1(1238.09,2842.62) 1(1238.09,2850.22) 1(1238.09,2850.22) 1(1238.49,2787.78) 1(1238.49,2787.78) 1(1238.57,2961.58) 1(1238.57,2961.58) 1(1238.89,2774.74) 1(1238.89,2774.74) 1(1239.25,2768.42) 1(1239.25,2768.42) 1(1239.25,3027.18) 1(1239.25,3027.18) 1(1239.41,2784.02) 1(1239.41,2784.02) 1(1239.41,2784.86) 1(1239.41,2784.86) 1(1239.65,2839.22) 1(1239.65,2839.22) 1(1239.65,2853.58) 1(1239.65,2853.58) 1(1239.69,2780.26) 1(1239.69,2780.26) 1(1239.69,2831.9) 1(1239.69,2831.9) 1(1239.69,2860.9) 1(1239.69,2860.9) 1(1239.89,2793.78) 1(1239.89,2793.78) 1(1239.93,2771.46) 1(1239.93,2771.46) 1(1240.05,2761.74) 1(1240.05,2761.74) 1(1242.25,2836.82) 1(1242.25,2836.82) 1(1242.25,2855.98) 1(1242.25,2855.98) 1(1243.17,3042.78) 1(1243.17,3042.78) 1(1243.21,2778.94) 1(1243.21,2778.94) 1(1243.37,2792.18) 1(1243.37,2792.18) 1(1243.57,2762.54) 1(1243.57,2762.54) 1(1245.17,3046.02) 1(1245.17,3046.02) 1(1245.65,2777.06) 1(1245.65,2777.06) 1(1245.69,2789.26) 1(1245.69,2789.26) 1(1245.85,2764.62) 1(1245.85,2764.62) 1(1246.05,2830.74) 1(1246.05,2830.74) 1(1246.05,2835.9) 1(1246.05,2835.9) 1(1246.05,2856.9) 1(1246.05,2856.9) 1(1246.05,2862.06) 1(1246.05,2862.06) 1(1246.53,2784.02) 1(1246.53,2784.02) 1(1246.53,2784.74) 1(1246.53,2784.74) 1(1247.05,2774.34) 1(1247.05,2774.34) 1(1247.13,2767.5) 1(1247.13,2767.5) 1(1247.53,2770.62) 1(1247.53,2770.62) 1(1248.61,2977.22) 1(1248.61,2977.22) 1(1249.85,2836.82) 1(1249.85,2836.82) 1(1249.85,2855.98) 1(1249.85,2855.98) 1(1250.29,2980.66) 1(1250.29,2980.66) 1(1250.45,2762.58) 1(1250.45,2762.58) 1(1250.45,2769.34) 1(1250.45,2769.34) 1(1252.41,2831.9) 1(1252.41,2831.9) 1(1252.41,2860.9) 1(1252.41,2860.9) 1(1252.49,2839.22) 1(1252.49,2839.22) 1(1252.49,2853.58) 1(1252.49,2853.58) 1(1254.01,2842.62) 1(1254.01,2842.62) 1(1254.01,2850.22) 1(1254.01,2850.22) 1(1254.53,2846.42) 1(1254.53,2846.42) 1(1256.01,3009.26) 1(1256.01,3009.26) 1(1257.13,2835.14) 1(1257.13,2835.14) 1(1257.13,2857.66) 1(1257.13,2857.66) 1(1258.49,3012.18) 1(1258.49,3012.18) 1(1258.81,2948.46) 1(1258.81,2948.46) 1(1259.45,2952.34) 1(1259.45,2952.34) 1(1260.05,2840.14) 1(1260.05,2840.14) 1(1260.05,2852.7) 1(1260.05,2852.7) 1(1261.05,2846.42) 1(1261.05,2846.42) 1(1263.09,2872.58) 1(1263.09,2872.58) 1(1264.41,3027.26) 1(1264.41,3027.26) 1(1265.09,2769.34) 1(1265.09,2769.34) 1(1265.09,2803.58) 1(1265.09,2803.58) 1(1266.81,3030.26) 1(1266.81,3030.26) 1(1270.37,2872.58) 1(1270.37,2872.58) 1(1273.37,2762.58) 1(1273.37,2762.58) 1(1273.37,2803.58) 1(1273.37,2803.58) 1(1274.41,2831.54) 1(1274.41,2831.54) 1(1274.73,2962.06) 1(1274.73,2962.06) 1(1275.25,2991.7) 1(1275.25,2991.7) 1(1277.41,2964.7) 1(1277.41,2964.7) 1(1277.93,2994.42) 1(1277.93,2994.42) 1(1278.01,2841.18) 1(1278.01,2841.18) 1(1278.13,2841.18) 1(1278.13,2841.18) 1(1280.13,2951.94) 1(1280.13,2951.94) 1(1281.53,2957.9) 1(1281.53,2957.9) 1(1281.69,2831.54) 1(1281.69,2831.54) 1(1282.53,2943.82) 1(1282.53,2943.82) 1(1284.01,2939.3) 1(1284.01,2939.3) 1(1285.09,2949.62) 1(1285.09,2949.62) 1(1286.17,2872.58) 1(1286.17,2872.58) 1(1286.21,3008.26) 1(1286.21,3008.26) 1(1286.53,2941.1) 1(1286.53,2941.1) 1(1286.57,2938.46) 1(1286.57,2938.46) 1(1289.69,3010.18) 1(1289.69,3010.18) 1(1289.93,2862.9) 1(1289.93,2862.9) 1(1290.05,2862.9) 1(1290.05,2862.9) 1(1292.17,2956.98) 1(1292.17,2956.98) 1(1293.53,2872.58) 1(1293.53,2872.58) 1(1294.37,2762.58) 1(1294.37,2762.58) 1(1294.37,2803.58) 1(1294.37,2803.58) 1(1294.45,2971.06) 1(1294.45,2971.06) 1(1297.17,2950.78) 1(1297.17,2950.78) 1(1297.37,2973.54) 1(1297.37,2973.54) 1(1298.41,2831.54) 1(1298.41,2831.54) 1(1301.81,2841.18) 1(1301.81,2841.18) 1(1301.93,2841.18) 1(1301.93,2841.18) 1(1302.65,2762.58) 1(1302.65,2762.58) 1(1302.65,2803.58) 1(1302.65,2803.58) 1(1305.85,2831.54) 1(1305.85,2831.54) 1(1306.05,2987.46) 1(1306.05,2987.46) 1(1307.13,2796.82) 1(1307.13,2796.82) 1(1307.13,2803.58) 1(1307.13,2803.58) 1(1308.37,2950.78) 1(1308.37,2950.78) 1(1309.33,2872.58) 1(1309.33,2872.58) 1(1310.45,2988.22) 1(1310.45,2988.22) 1(1313.49,2945.14) 1(1313.49,2945.14) 1(1316.09,2762.58) 1(1316.09,2762.58) 1(1316.09,2796.82) 1(1316.09,2796.82) 1(1316.65,2872.58) 1(1316.65,2872.58) 1(1323.49,2965.46) 1(1323.49,2965.46) 1(1324.29,2946.06) 1(1324.29,2946.06) 1(1324.37,2762.58) 1(1324.37,2762.58) 1(1324.37,2796.82) 1(1324.37,2796.82) 1(1328.53,2964.94) 1(1328.53,2964.94) 1(1328.81,2940.94) 1(1328.81,2940.94) 1(1333.33,2796.82) 1(1333.33,2796.82) 1(1333.33,2803.58) 1(1333.33,2803.58) 1(1334.73,2319.22) 1(1334.73,2319.22) 1(1338.17,2942.66) 1(1338.17,2942.66) 1(1341.53,2206.75) 1(1341.53,2326.02) 1(1341.53,2326.02) 1(1341.53,2938.06) 1(1341.53,2938.06) 1(1341.65,2326.02) 1(1343.57,2940.86) 1(1343.57,2940.86) 1(1345.57,2937.22) 1(1345.57,2937.22) 1(1348.45,2319.22) 1(1348.45,2319.22) 1(1387.33,2728.78) 1(1387.33,2728.78) 1(1387.33,2903.18) 1(1387.33,2903.18) 1(1387.45,2728.7) 1(1387.45,2728.7) 1(1387.45,2903.14) 1(1387.45,2903.14) 1(1394.93,2721.18) 1(1394.93,2721.18) 1(1394.93,3213.22) 1(1394.93,3213.22) 1(1431.38,2011.75) 1(1431.38,2011.75) 1(1438.92,2004.22) 1(1439.75,2004.22) 1(1439.75,2004.22) 1(1439.75,2154.22) 1(1447.29,2011.75) 1(1447.29,2011.75) 1(1455.43,-1057.06) 1(1455.43,-1057.06) 1(1457.76,-555.79) 1(1457.76,-555.79) 1(1545.75,1871.75) 1(1581.41,1871.75) 1(1581.41,1871.75) 1(1593.38,1808.22) 1(1601.94,1851.22) 1(1602.83,1798.77) 1(1602.83,1798.77) 1(1617.38,1798.77) 1(1627.07,-235.55) 1(1627.07,-208.47) 1(1627.07,-208.47) 1(1634.28,-201.25) 1(1691.28,-287.25) 1(1691.28,-272.25) 1(1691.28,-272.25) 1(1702.28,-261.25) 1(1702.28,-261.25) 1(1702.28,-215.25) 1(1702.28,-215.25) 1(1724.28,-193.25) 1(1854.28,1442.75) 1(1867.28,1442.75) 1(1867.28,1442.75) 1(1882.28,1771.75) 1(1893.28,1468.75) 1(1893.28,1771.75) 1(1939.28,1426.6) 1(1947.15,1434.47) 1(1947.15,1434.47) 1(1984.01,1434.47) 1(1984.01,1434.47) 1(1986.38,1672.22) 1(1996.35,1662.25) 1(1996.35,1662.25) 1(1997.7,1448.16) 1(1997.7,1448.16) 1(2006.78,1662.25) 1(2006.78,1662.25) 1(2010.7,1448.16) 1(2010.7,1448.16) 1(2012.28,1592.75) 1(2022.28,1592.75) 1(2022.28,1592.75) 1(2023.28,1645.75) 1(2023.28,1645.75) 1(2028.28,1465.75) 1(2028.28,1465.75) 1(2028.28,1490.75) 1(2034.52,1128.27) 1(2044.28,1624.75) 1(2050.28,1564.75) 1(2068.52,1128.27) 1(2105.11,950.26) 1(2105.11,950.26) 1(2105.11,981.76) 1(2105.11,981.76) 1(2105.11,985.26) 1(2105.11,985.26) 1(2105.11,1016.76) 1(2105.11,1016.76) 1(2118.28,1829.75) 1(2121.18,820.75) 1(2121.18,834.72) 1(2125.28,1822.75) 1(2125.28,1822.75) 1(2125.64,950.26) 1(2125.64,981.76) 1(2125.64,985.26) 1(2125.64,1016.76) 1(2143.64,950.26) 1(2143.64,981.76) 1(2143.64,985.26) 1(2143.64,1016.76) 1(2164.17,950.26) 1(2164.17,950.26) 1(2164.17,981.76) 1(2164.17,981.76) 1(2164.17,985.26) 1(2164.17,985.26) 1(2164.17,1016.76) 1(2164.17,1016.76) 1(2164.28,1822.75) 1(2289.28,2206.75) 1(2296.28,2213.75) 1(2296.28,2213.75) 1(2302.28,2213.75) 1(2325,1886.74) 1(2325,1886.74) 1(2325,1907.26) 1(2325,1925.26) 1(2325,1945.79) 1(2325,1945.79) 1(2355.43,-1057.06) 1(2355.43,-1057.06) 1(2356.5,1886.74) 1(2356.5,1886.74) 1(2356.5,1907.26) 1(2356.5,1925.26) 1(2356.5,1945.79) 1(2356.5,1945.79) 1(2357.76,-555.79) 1(2357.76,-555.79) 1(2405.28,885.75) 1(2405.28,1065.75) 1(2405.28,1065.75) 1(2423.28,1083.75) 1(2423.28,1083.75) 1(2425.3,865.73) 1(2464.28,3361.75) 1(2466.28,1126.75) 1(2466.28,1135.75) 1(2469.18,822.62) 1(2474.28,827.75) 1(2474.28,827.75) 1(2476.28,3361.75) 1(2476.28,3361.75) 1(2484.28,3353.75) 1(2512.88,827.75) 1(2514.28,1154.75) 1(2535.28,1154.75) 1(2535.28,1154.75) 1(2547.28,1142.75) 1(2596.28,1083.75) 1(2596.28,1083.75) 1(2599.27,865.73) 1(2599.27,865.73) 1(2599.28,58.75) 1(2599.28,58.75) 1(2599.28,264.75) 1(2599.28,264.75) 1(2604.88,1105.15) 1(2614.28,43.75) 1(2614.28,43.75) 1(2615.28,881.75) 1(2615.28,881.75) 1(2615.28,1064.75) 1(2615.28,1064.75) 1(2617.28,282.75) 1(2617.28,282.75) 1(2672.88,1105.15) 1(2728.39,323.75) 1(2740.28,1549.75) 1(2740.28,1549.75) 1(2740.28,1579.75) 1(2763.78,1526.25) 1(2780.85,1511.47) 1(2780.85,1511.47) 1(2780.85,1542.96) 1(2780.85,1542.96) 1(2792.17,323.75) 1(2801.37,1511.47) 1(2801.37,1542.96) 1(2817.28,282.75) 1(2817.28,282.75) 1(2819.37,1511.47) 1(2819.37,1542.96) 1(2823.28,43.75) 1(2823.28,43.75) 1(2835.28,55.75) 1(2835.28,55.75) 1(2835.28,264.75) 1(2835.28,264.75) 1(2839.9,1511.47) 1(2839.9,1511.47) 1(2839.9,1542.96) 1(2839.9,1542.96)
  round 3.9 on Mech16: 1(599.22,-807.26) 1(599.22,-746.2) 1(599.22,-609.51) 1(599.22,-548.45) 1(599.22,-409.65) 1(599.22,-348.59) 1(660.28,-807.26) 1(660.28,-746.2) 1(660.28,-609.51) 1(660.28,-548.45) 1(660.28,-409.65) 1(660.28,-348.59) 1(741.48,1031.5) 1(741.48,1053.98) 1(741.48,1089.77) 1(741.48,1112.25) 1(749.39,1031.5) 1(749.39,1053.98) 1(749.39,1089.77) 1(749.39,1112.25) 1(755.85,-529.32) 1(755.85,-468.25) 1(761.17,1031.5) 1(761.17,1053.98) 1(761.17,1089.77) 1(761.17,1112.25) 1(769.08,1031.5) 1(769.08,1053.98) 1(769.08,1089.77) 1(769.08,1112.25) 1(780.85,1031.5) 1(780.85,1053.98) 1(780.85,1089.77) 1(780.85,1112.25) 1(788.76,1031.5) 1(788.76,1053.98) 1(788.76,1089.77) 1(788.76,1112.25) 1(816.91,-529.32) 1(816.91,-468.25) 1(905.85,-751.32) 1(905.85,-690.25) 1(966.91,-751.32) 1(966.91,-690.25) 1(1248.48,1698.28) 1(1248.48,1725.87) 1(1248.48,1798.67) 1(1248.48,1826.27) 1(1266.24,1698.28) 1(1266.24,1725.87) 1(1266.24,1798.67) 1(1266.24,1826.27) 1(1285.88,1698.28) 1(1285.88,1725.87) 1(1285.88,1798.67) 1(1285.88,1826.27) 1(1296.48,199.68) 1(1296.48,260.75) 1(1303.64,1698.28) 1(1303.64,1725.87) 1(1303.64,1798.67) 1(1303.64,1826.27) 1(1323.28,1698.28) 1(1323.28,1725.87) 1(1323.28,1798.67) 1(1323.28,1826.27) 1(1341.04,1698.28) 1(1341.04,1725.87) 1(1341.04,1798.67) 1(1341.04,1826.27) 1(1357.54,199.68) 1(1357.54,260.75) 1(1565.85,-534.32) 1(1565.85,-473.25) 1(1626.91,-534.32) 1(1626.91,-473.25) 1(2248.89,963.27) 1(2248.89,985.35) 1(2290.22,-217.26) 1(2290.22,-156.2) 1(2333.18,963.27) 1(2333.18,985.35) 1(2351.28,-217.26) 1(2351.28,-156.2) 1(2395.22,-462.26) 1(2395.22,-401.2) 1(2456.28,-462.26) 1(2456.28,-401.2)
  round 15.75 on Mech16: 1(784.81,1059.08)
  round 157.48 on Mech16: 1(800.75,2823.27) 1(800.75,3571.3) 1(800.75,3889.98) 1(2729.89,2823.27) 1(2729.89,3571.3) 1(2729.89,3889.98)
  round 23.98 on Mech16: 1(885.28,1523.73)
  round 19.68 on Mech16: 1(922.1,1075.65) 1(1089.63,1249.51) 1(1096.63,1399.56) 1(1173.37,923.62) 1(1177.37,1104.62) 1(1402.76,890.87) 1(1791.78,903.14) 1(2646.88,839.71)
  round 51 on Mech16: 1(1019.88,2921.16) 1(1019.88,3649.16) 1(2311.38,2921.16) 1(2311.38,3649.16)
